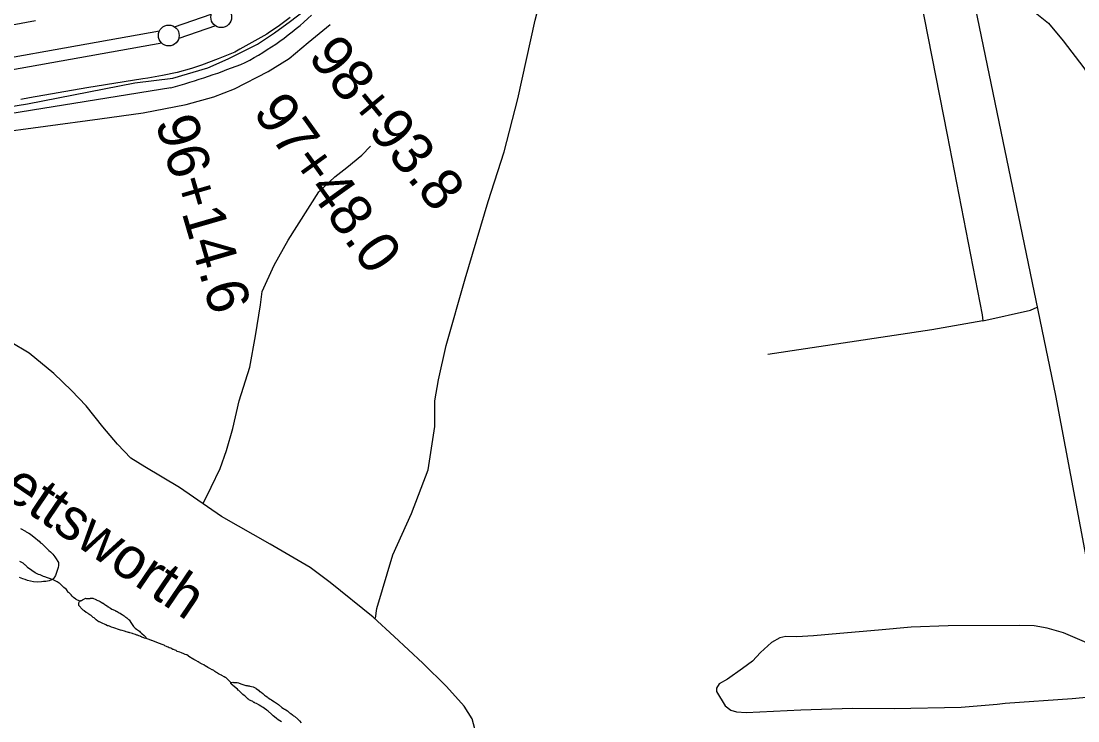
# Model space of a CAD drawing. Extents: x 3146026 to 3183936, y 897894 to 923344.
# Drawn here: x 3162279 to 3164815, y 909503 to 911183 of the extents above; entities that cross this region are included whole.
import ezdxf

# ---------------------------------------------------------------- set-up
doc = ezdxf.new("R2010")
doc.units = 0
for name, color, linetype in [('V-LEVE-TOET', 7, 'Continuous'), ('V-RIVR-IDEN', 7, 'Continuous'), ('V-ROAD-CNTR', 7, 'Continuous'), ('V-SITE-VEGE', 7, 'Continuous'), ('V-SURV-IDEN', 7, 'Continuous'), ('V-SURV-LINE', 7, 'Continuous'), ('V-TOPO-SHOR', 7, 'Continuous')]:
    doc.layers.add(name, color=color, linetype=linetype)

msp = doc.modelspace()

# ---------------------------------------------------------------- linework, layer by layer
at = {"layer": 'V-LEVE-TOET'}
for points in [[(3162313.2, 911183.9), (3162257.1, 911173.5)], [(3162925, 911192.1), (3162899, 911172.7), (3162872, 911154.6), (3162868.5, 911152.4), (3162804.2, 911115.8), (3162791.5, 911108.8), (3162752, 911092.5), (3162712, 911077.6), (3162687.6, 911069.5), (3162653.2, 911060.2), (3162618.4, 911052.5), (3162583.3, 911046.4), (3162570.8, 911044.6), (3162436.5, 911023.4), (3162298.7, 910999.1), (3162277.9, 910995.3)]]:
    msp.add_lwpolyline(points, dxfattribs=at)
at = {"layer": 'V-ROAD-CNTR'}
msp.add_lwpolyline([(3162638.2, 911023.4), (3161582.1, 910852.6), (3160471.1, 910632.1), (3159717.3, 910482.4)], dxfattribs=at)
for centre, radius, start, end in [((3162478.8, 911723.2), 723.2, 297.8732, 313.3998), ((3162231.5, 912517.7), 1548.6, 285.2231, 292.2089)]:
    msp.add_arc(centre, radius, start, end, dxfattribs=at)
at = {"layer": 'V-SITE-VEGE'}
msp.add_lwpolyline([(3162277.3, 909964.6), (3162289, 909958.8), (3162291.1, 909957.1), (3162297.5, 909953.4), (3162301.7, 909951.7), (3162305.9, 909947.5), (3162313.5, 909941.7), (3162318.9, 909936.7), (3162321.9, 909934.6), (3162325.3, 909930.8), (3162328.2, 909928.8), (3162341.7, 909916.3), (3162345.5, 909912.5), (3162349.3, 909909.2), (3162351.4, 909906.7), (3162354.8, 909903.3), (3162359.4, 909897.1), (3162361.6, 909894.5), (3162368.8, 909883.3), (3162368.8, 909876.1), (3162368, 909871.5), (3162361.4, 909851.8), (3162357.6, 909845.9), (3162355.1, 909843.3), (3162351.4, 909841.6), (3162345.9, 909839.5), (3162338.4, 909837.8), (3162332.5, 909837.3), (3162327.5, 909836.5), (3162317.4, 909836), (3162308.6, 909836.8), (3162294.3, 909840), (3162288.4, 909842.5), (3162283, 909844.2), (3162275, 909847.5)], dxfattribs=at)
at = {"layer": 'V-SURV-LINE'}
for points in [[(3162647.2, 911169.6), (3162735.4, 911200.4)], [(3160812, 910838.1), (3162611, 911160.1)], [(3162745.3, 911172.1), (3162657.1, 911141.3)], [(3162616.3, 911130.6), (3160817.3, 910808.6)]]:
    msp.add_lwpolyline(points, dxfattribs=at)
for centre in [(3162759.2, 911192.9), (3162633.3, 911148.9)]:
    msp.add_circle(centre, 25, dxfattribs=at)
at = {"layer": 'V-TOPO-SHOR'}
for points in [[(3162040.6, 910943.7), (3162294.1, 910984.7), (3162552.1, 911035.1), (3162642.8, 911046.3), (3162727, 911071.4), (3162776.2, 911093.1), (3162846.2, 911128), (3162886.9, 911155), (3162925.2, 911183), (3163020.1, 911256.4), (3163191.7, 911394.3), (3163241.4, 911436.5), (3163506.4, 911654.6), (3163712.7, 911817.2), (3163793.6, 911875.6), (3163816.2, 911892.1), (3163892.9, 911921.6), (3164045, 911969.6), (3164168.8, 912005.6), (3164269.3, 912034.5)], [(3163129.8, 909750), (3163132.5, 909772.7), (3163171.1, 909902), (3163216.1, 910001.1), (3163256.1, 910105.6), (3163272.3, 910209.6), (3163271.8, 910271.7), (3163280.4, 910322.1), (3163299.1, 910404.4), (3163344.7, 910564.5), (3163400.3, 910750.3), (3163438.6, 910869.3), (3163470.9, 910996.7), (3163513.1, 911185.9), (3163535, 911271.1), (3163546.6, 911318.4), (3163550.9, 911403.1), (3163546.5, 911471.5), (3163531.5, 911570.1)], [(3164332, 911489.1), (3164343.7, 911461.9), (3164357.7, 911445), (3164374, 911434.2), (3164393.2, 911420.2), (3164402.3, 911408.6), (3164409.8, 911379.5), (3164501.9, 910910.6), (3164585.7, 910478.1), (3164587.3, 910463.6), (3164701.8, 910489.5), (3164717.5, 910496.3)], [(3164550.5, 911305.4), (3164761.6, 910284.2), (3164890.4, 909600.2), (3165034.8, 908874.5), (3165047.7, 908814.1), (3165042.2, 908764.6), (3164970.4, 908470.7), (3164847.8, 907979.5), (3164825.9, 907934.6), (3164802.4, 907904.2)], [(3164627.2, 911277.7), (3164713.2, 911204.4), (3164745, 911178.3), (3164780, 911136.4), (3164830, 911071.3), (3164884.3, 910984.4), (3164898.2, 910962.3), (3164906.5, 910956.1), (3164924.2, 910944.8)], [(3161817.9, 910855), (3162205.8, 910913.4), (3162468, 910948.7), (3162571.9, 910962.8), (3162674.7, 910982.9), (3162741.4, 911001.6), (3162791.3, 911020.8), (3162871.8, 911062), (3162922, 911093.2), (3162967.5, 911131.7), (3163020.4, 911174.9)], [(3162716.1, 910024.6), (3162734.7, 910064.5), (3162756.6, 910109.4), (3162772.2, 910152.4), (3162787, 910204.8), (3162802.2, 910271.6), (3162828.2, 910352.6), (3162841.5, 910427.8), (3162853.8, 910501.9), (3162857.8, 910533.9), (3162886.3, 910597.3), (3162920, 910657.4), (3162993.4, 910773.4), (3163031.5, 910809.6), (3163061.1, 910831.6), (3163097, 910861.7), (3163117.2, 910882.9)], [(3164587.3, 910463.6), (3164464.7, 910442), (3164071.2, 910383)], [(3163343.6, 909265.5), (3163366.8, 909398.3), (3163371.4, 909457.1), (3163368, 909484.1), (3163361.4, 909508.1), (3163342.5, 909538.6), (3163300.3, 909585.2), (3163242.8, 909641.5), (3163174.2, 909705.4), (3163123.7, 909752.2), (3163020.4, 909835.6), (3162972.7, 909871), (3162877, 909927.3), (3162759.8, 909993.5), (3162659.2, 910063.4), (3162575.7, 910113.1), (3162542.1, 910133.7), (3162509.9, 910167.6), (3162474.8, 910208.9), (3162434.7, 910259.6), (3162399.5, 910296.7), (3162357.1, 910337.1), (3162298.5, 910386.2), (3162252.6, 910413.3)], [(3162419.6, 909790.4), (3162411, 909794.6), (3162409.9, 909795.6), (3162404.2, 909799.2), (3162401, 909802.5), (3162399.3, 909805.5), (3162397.6, 909807.6), (3162394.4, 909810.1), (3162392.9, 909811.6), (3162391.7, 909812.2), (3162387.6, 909818.3), (3162384.2, 909820.6), (3162381.7, 909822.9), (3162376.8, 909828.4), (3162374.3, 909830.7), (3162371.7, 909832.8), (3162370.2, 909833.6), (3162365.4, 909836.9), (3162357.1, 909840.9), (3162353.5, 909842.2), (3162346.7, 909844.9), (3162344.2, 909845.7), (3162342.3, 909846.7), (3162335.5, 909848.8), (3162332.4, 909850.1), (3162324.5, 909853.4), (3162320.5, 909854.8), (3162317.1, 909856.5), (3162312.3, 909858.6), (3162304.4, 909863.8), (3162294.5, 909871.4), (3162293.6, 909872.2), (3162292.4, 909873.9), (3162289.2, 909877.3), (3162287.9, 909878.1), (3162284.1, 909881.7), (3162275.6, 909885.8)], [(3162581.7, 909699.8), (3162577.9, 909700.7), (3162574.9, 909701.9), (3162573.7, 909702.7), (3162570.7, 909703.5), (3162569, 909704.4), (3162567.8, 909704.8), (3162566.5, 909705.6), (3162565.3, 909705.6), (3162564.4, 909706.4), (3162561.5, 909707.3), (3162558.1, 909708.5), (3162556.9, 909708.5), (3162553.1, 909710.2), (3162547.6, 909711.8), (3162545.9, 909712.6), (3162539.6, 909714.7), (3162537.9, 909715.1), (3162536.3, 909715.1), (3162534.2, 909716.4), (3162531.2, 909717.2), (3162529.5, 909718), (3162527.4, 909718.4), (3162521.5, 909720.1), (3162517.8, 909720.9), (3162510.6, 909723.4), (3162506, 909724.6), (3162503.9, 909725.4), (3162501, 909726.2), (3162495.9, 909728.3), (3162494.2, 909728.7), (3162490.9, 909730.4), (3162488.8, 909731.2), (3162487.5, 909731.6), (3162485.8, 909731.6), (3162482.5, 909733.3), (3162480.8, 909734.5), (3162478.7, 909735.3), (3162475.3, 909737), (3162470.3, 909739.1), (3162468.6, 909739.9), (3162467.3, 909740.7), (3162465.6, 909741.1), (3162462.7, 909742.8), (3162458.9, 909745.7), (3162455.5, 909748.6), (3162454.2, 909750.3), (3162452.1, 909751.6), (3162447.9, 909755.3), (3162446.7, 909755.7), (3162445, 909757), (3162444.1, 909757.8), (3162441.6, 909759.1), (3162439.9, 909760.7), (3162437.8, 909761.5), (3162437, 909762.4), (3162434.9, 909763.2), (3162429.8, 909767), (3162429, 909767.8), (3162427.7, 909768.6), (3162426.9, 909769.9), (3162423.9, 909772.8), (3162422.6, 909773.6), (3162421.8, 909774.5), (3162421.4, 909775.7), (3162417.6, 909779.9), (3162417.6, 909781.6), (3162417.1, 909782.8), (3162417.5, 909784.9), (3162417.5, 909786.2), (3162418, 909787.9), (3162418.8, 909789.6), (3162419.6, 909790.4)], [(3162419.6, 909790.4), (3162420.9, 909790.8), (3162422.1, 909791.7), (3162423.4, 909792.1), (3162425.9, 909793.8), (3162432.6, 909797.2), (3162433.4, 909798), (3162434.7, 909797.2), (3162444.3, 909797.2), (3162445.6, 909797.7), (3162448.5, 909797.3), (3162451, 909797.3), (3162457.8, 909794.4), (3162459.5, 909794), (3162460.7, 909793.1), (3162463.2, 909792.3), (3162465.3, 909791.1), (3162468.7, 909789.8), (3162470.8, 909788.2), (3162474.6, 909785.7), (3162475.9, 909785.3), (3162480.1, 909782.8), (3162481.8, 909781.1), (3162486.4, 909778.2), (3162487.2, 909776.9), (3162488.5, 909776.5), (3162490.2, 909775.3), (3162491.9, 909774.4), (3162493.1, 909774), (3162496.5, 909771.5), (3162498.6, 909770.7), (3162504.5, 909767.8), (3162506.2, 909766.5), (3162507.9, 909766.6), (3162509.5, 909765.3), (3162514.2, 909762.4), (3162516.3, 909761.6), (3162519.6, 909759.5), (3162521.3, 909758.2), (3162526.4, 909755.3), (3162527.2, 909754.1), (3162528.9, 909753.2), (3162530.2, 909752.4), (3162532.3, 909750.3), (3162533.5, 909749.5), (3162536.5, 909746.6), (3162538.2, 909745.3), (3162539.5, 909743.2), (3162542.4, 909739.5), (3162548.3, 909729.9), (3162551.7, 909726.5), (3162553, 909725.7), (3162555.9, 909723.2), (3162558, 909721.9), (3162562.7, 909718.2), (3162564.4, 909716.1), (3162566, 909715.3), (3162567.3, 909714), (3162568.6, 909713.2), (3162574.1, 909707.8), (3162575.3, 909706.9), (3162581.7, 909699.8)], [(3164876.3, 909673.5), (3164780.7, 909714.8), (3164742.2, 909725.7), (3164710.8, 909731.1), (3164674.6, 909732.1), (3164504.5, 909730.9), (3164415.4, 909728), (3164336.6, 909720.8), (3164244.4, 909712.9), (3164181.1, 909707.3), (3164141.2, 909704.7), (3164114.4, 909705.5), (3164100.3, 909702.2), (3164080.4, 909691.4), (3164053.9, 909667.2), (3164034.2, 909646.5), (3164010.5, 909629.1), (3163974.6, 909603.1), (3163954.2, 909591.8), (3163947.7, 909581.6), (3163948, 909573.8), (3163968.8, 909539.1), (3163982.5, 909529), (3163995.8, 909524.5), (3164019.1, 909523.3), (3164150.1, 909529.7), (3164274.8, 909533.2), (3164374.6, 909533.1), (3164535, 909536.1), (3164622.1, 909543.2), (3164640.8, 909545.8), (3164801.9, 909556.5), (3164896.2, 909565.4)], [(3162782.4, 909595.2), (3162770.1, 909606.9), (3162768.9, 909607.3), (3162766.4, 909609), (3162760.9, 909611.9), (3162759.6, 909612.7), (3162757.5, 909613.5), (3162752.5, 909616), (3162750.4, 909617.3), (3162749.5, 909618.1), (3162747.8, 909618.9), (3162746.2, 909620.2), (3162744.1, 909621.4), (3162741.1, 909623.9), (3162739.8, 909624.4), (3162738.6, 909625.2), (3162737.3, 909625.6), (3162731.8, 909628.9), (3162726.8, 909631.4), (3162723.8, 909633.5), (3162721.3, 909634.7), (3162717.1, 909637.2), (3162713.7, 909638.9), (3162710.4, 909641), (3162709.5, 909641.8), (3162707.4, 909642.6), (3162706.6, 909643.5), (3162704.1, 909644.7), (3162698.6, 909648), (3162696.5, 909648.4), (3162693.5, 909650.1), (3162689.3, 909653), (3162688.1, 909653.4), (3162685.1, 909655.1), (3162683.9, 909656.3), (3162676.3, 909661.3), (3162672.9, 909662.6), (3162669.1, 909664.2), (3162664.1, 909666.7), (3162659.5, 909668), (3162656.9, 909669.2), (3162653.6, 909670), (3162651, 909671.7), (3162648.5, 909672.5), (3162644.7, 909674.2), (3162643.1, 909674.6), (3162640.5, 909676.2), (3162638, 909677.5), (3162634.2, 909678.7), (3162631.7, 909680), (3162629.6, 909680.8), (3162627.5, 909682), (3162624.1, 909683.3), (3162622.4, 909684.5), (3162617.4, 909686.2), (3162611.1, 909688.7), (3162593, 909696.1), (3162591.7, 909696.1), (3162590.1, 909696.9), (3162587.5, 909697.8), (3162585.9, 909698.6), (3162581.7, 909699.8)], [(3162794.8, 909581.3), (3162789.9, 909585.9), (3162787, 909588.2), (3162785.9, 909589.3), (3162784.8, 909589.9), (3162783.8, 909590.9), (3162782.3, 909593), (3162781.9, 909594.1), (3162782.4, 909595.2)], [(3162782.4, 909595.2), (3162785.3, 909595.2), (3162787, 909595.7), (3162788.3, 909595.3), (3162792.9, 909595.3), (3162794.1, 909594.9), (3162797.1, 909594.9), (3162800.8, 909594.1), (3162802.5, 909593.2), (3162804.6, 909592.8), (3162806.3, 909592), (3162818.5, 909588.3), (3162820.2, 909587.9), (3162821.4, 909587.9), (3162823.1, 909587.1), (3162826.1, 909587.1), (3162828.2, 909586.2), (3162836.1, 909584.6), (3162840.4, 909582.1), (3162842.5, 909581.3), (3162843.3, 909580.5), (3162848.4, 909576.7), (3162851.3, 909573.8), (3162852.6, 909573.4), (3162854.7, 909572.1), (3162858.9, 909568.8), (3162862.7, 909565), (3162865.6, 909563.4), (3162869.8, 909560.5), (3162870.7, 909559.2), (3162873.6, 909557.5), (3162876.6, 909555.5), (3162879.5, 909553.8), (3162885.4, 909549.6), (3162886.7, 909548.4), (3162896.4, 909542.1), (3162904.8, 909535.1), (3162908.6, 909533), (3162910.3, 909531.3), (3162911.5, 909531.3), (3162912.8, 909530.1), (3162914.5, 909529.2), (3162917.9, 909527.2), (3162920, 909525.5), (3162922.9, 909522.6), (3162926.3, 909520.5), (3162930.5, 909517.6), (3162933, 909515.1), (3162934.7, 909514.3), (3162943.1, 909507.2), (3162944.4, 909505.5), (3162946.9, 909503.4), (3162951.2, 909498.4)], [(3162903.9, 909500.4), (3162896.1, 909505.5), (3162891.9, 909508.6), (3162886.8, 909513), (3162884.2, 909515.5), (3162879.8, 909518.9), (3162871.7, 909526.2), (3162869.2, 909527.9), (3162867.7, 909529.4), (3162864.1, 909532.1), (3162862.8, 909532.7), (3162859.9, 909534.8), (3162856.9, 909536.5), (3162854.1, 909538.6), (3162850.3, 909540.9), (3162849.3, 909541.7), (3162844.2, 909544.4), (3162840.8, 909545.9), (3162839.3, 909546.9), (3162837.6, 909547.5), (3162834.9, 909549.2), (3162833.8, 909550.1), (3162831.3, 909551.1), (3162829.6, 909552.1), (3162827.3, 909553), (3162825.8, 909554), (3162824.9, 909554.9), (3162823.9, 909555.3), (3162820.3, 909558.4), (3162819.6, 909559.3), (3162818.8, 909559.9), (3162816.9, 909562), (3162813.9, 909564.3), (3162811.4, 909566.6), (3162809.9, 909567.4), (3162805.2, 909572.3), (3162803.7, 909573.3), (3162801.6, 909575.6), (3162800.5, 909576.3), (3162798, 909578.8), (3162794.8, 909581.3)]]:
    msp.add_lwpolyline(points, dxfattribs=at)

# ---------------------------------------------------------------- texts
at = {"layer": 'V-RIVR-IDEN'}
msp.add_text('Bayou   Lettsworth', height=100, rotation=325.8517, dxfattribs=at).set_placement((3161760.3, 910364.6))
at = {"layer": 'V-SURV-IDEN'}
for s, rotation, p in [('98+93.8', 309.3572, (3162964.9, 911096.4)), ('97+48.0', 305.6603, (3162833.3, 910964.4)), ('96+14.6', 286.1738, (3162600.7, 910941.9))]:
    msp.add_text(s, height=100, rotation=rotation, dxfattribs=at).set_placement(p)

doc.saveas('drawing.dxf')
